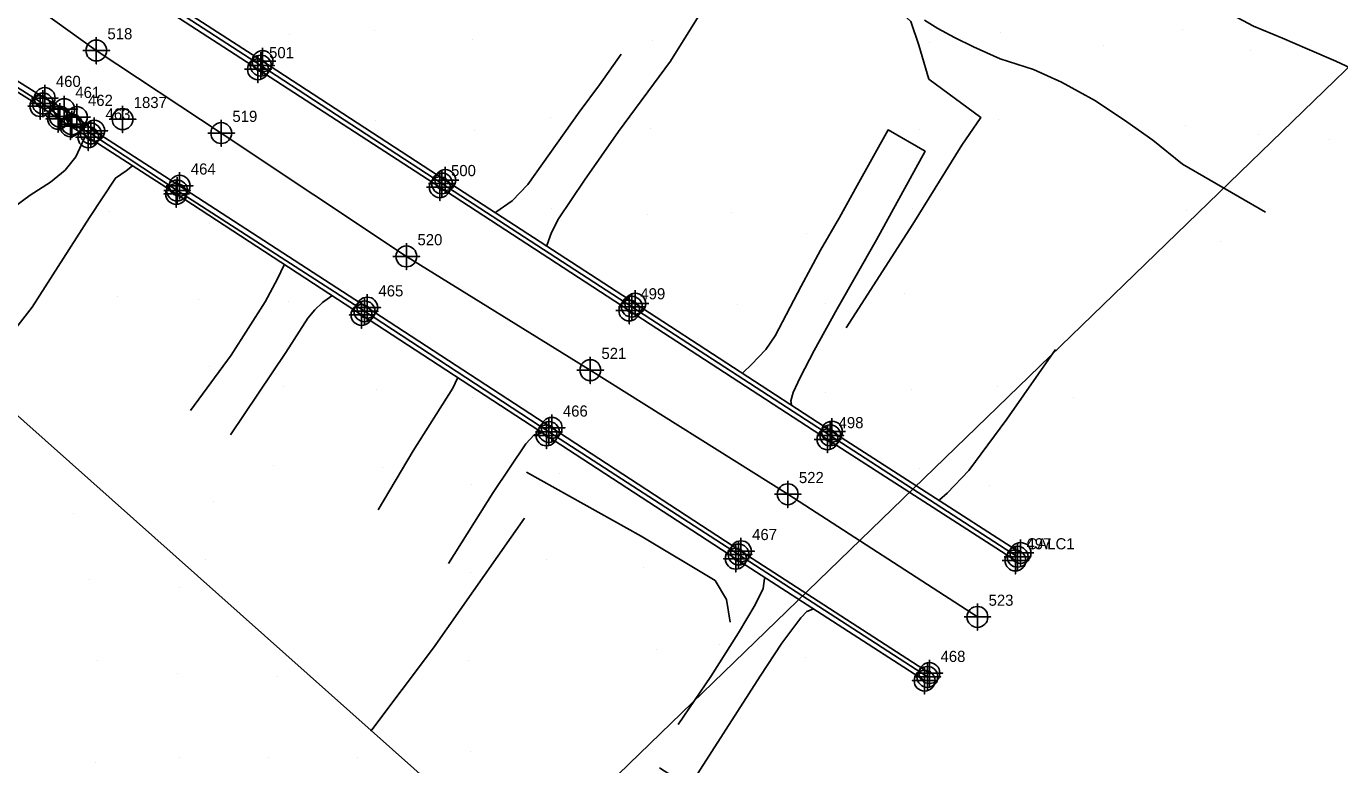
# Model space of a CAD drawing. Extents: x 1497074 to 1501343, y 481943 to 486114.
# Drawn here: x 1498449.4 to 1498743.8, y 484461 to 484626.5 of the extents above; entities that cross this region are included whole.
import ezdxf

# ---------------------------------------------------------------- set-up
doc = ezdxf.new("R2010")
doc.units = 0
for name, color, linetype in [('Exist DTM Crownline', 7, 'Continuous'), ('Exist DTM Crownline Cogo Number', 7, 'Continuous'), ('Exist DTM Crownline Cogo Point CELL', 7, 'Continuous'), ('Exist DTM Drainline', 7, 'Continuous'), ('Exist DTM Drainline Cogo Point CELL', 7, 'Continuous'), ('Exist DTM Regular Point CELL', 7, 'Continuous'), ('Exist DTM Regular Point Cogo Number', 7, 'Continuous'), ('Exist Roads Curbs', 7, 'Continuous'), ('Exist Roads Curbs Cogo Point CELL', 7, 'Continuous'), ('Exist Roads EOP', 7, 'Continuous'), ('Exist Roads EOP Cogo Number', 7, 'Continuous'), ('Exist Roads EOP Cogo Point CELL', 7, 'Continuous'), ('PH Exist DTM Boundary', 7, 'Continuous'), ('PH Exist DTM Breakline', 7, 'Continuous'), ('PH Exist DTM Point', 7, 'Continuous')]:
    doc.layers.add(name, color=color, linetype=linetype)

msp = doc.modelspace()

# ---------------------------------------------------------------- linework, layer by layer
at = {"layer": 'Exist DTM Crownline'}
msp.add_lwpolyline([(1498437.44, 484640.31), (1498444.09, 484636.17), (1498465.05, 484621.1), (1498493.07, 484602.59), (1498534.57, 484574.94), (1498575.81, 484549.45), (1498620.08, 484521.62), (1498662.61, 484494.12)], dxfattribs=at)
at = {"layer": 'Exist DTM Crownline Cogo Point CELL'}
for points in [[(1498465.05, 484624.1), (1498465.05, 484618.1), (1498465.05, 484621.1), (1498468.05, 484621.1), (1498462.05, 484621.1)], [(1498493.07, 484605.59), (1498493.07, 484599.59), (1498493.07, 484602.59), (1498496.07, 484602.59), (1498490.07, 484602.59)], [(1498534.57, 484577.94), (1498534.57, 484571.94), (1498534.57, 484574.94), (1498537.57, 484574.94), (1498531.57, 484574.94)], [(1498575.81, 484552.45), (1498575.81, 484546.45), (1498575.81, 484549.45), (1498578.81, 484549.45), (1498572.81, 484549.45)], [(1498620.08, 484524.62), (1498620.08, 484518.62), (1498620.08, 484521.62), (1498623.08, 484521.62), (1498617.08, 484521.62)], [(1498662.61, 484497.12), (1498662.61, 484491.12), (1498662.61, 484494.12), (1498665.61, 484494.12), (1498659.61, 484494.12)]]:
    msp.add_lwpolyline(points, dxfattribs=at)
for centre in [(1498465.05, 484621.1), (1498493.07, 484602.59), (1498534.57, 484574.94), (1498575.81, 484549.45), (1498620.08, 484521.62), (1498662.61, 484494.12)]:
    msp.add_circle(centre, 2.34, dxfattribs=at)
at = {"layer": 'Exist DTM Drainline'}
for points in [[(1498671.61, 484507.62), (1498629.62, 484534.81), (1498585.12, 484563.67), (1498542.56, 484591.3), (1498501.94, 484617.72), (1498481.42, 484631.07), (1498478.45, 484633.67)], [(1498456.84, 484606.28), (1498453.09, 484609.22), (1498440.58, 484617.04), (1498437.69, 484618.27), (1498435.85, 484618.97), (1498433.34, 484619.71), (1498431.51, 484619.86)], [(1498651.39, 484480.67), (1498609.06, 484508.13), (1498566.53, 484535.59), (1498525.19, 484562.64), (1498483.16, 484589.73), (1498463.82, 484602.49), (1498459.58, 484604.56)]]:
    msp.add_lwpolyline(points, dxfattribs=at)
at = {"layer": 'Exist DTM Drainline Cogo Point CELL'}
for points in [[(1498501.94, 484620.72), (1498501.94, 484614.72), (1498501.94, 484617.72), (1498504.94, 484617.72), (1498498.94, 484617.72)], [(1498453.09, 484612.22), (1498453.09, 484606.22), (1498453.09, 484609.22), (1498456.09, 484609.22), (1498450.09, 484609.22)], [(1498456.84, 484609.28), (1498456.84, 484603.28), (1498456.84, 484606.28), (1498459.84, 484606.28), (1498453.84, 484606.28)], [(1498459.58, 484607.56), (1498459.58, 484601.56), (1498459.58, 484604.56), (1498462.58, 484604.56), (1498456.58, 484604.56)], [(1498463.82, 484605.49), (1498463.82, 484599.49), (1498463.82, 484602.49), (1498466.82, 484602.49), (1498460.82, 484602.49)], [(1498542.56, 484594.3), (1498542.56, 484588.3), (1498542.56, 484591.3), (1498545.56, 484591.3), (1498539.56, 484591.3)], [(1498483.16, 484592.73), (1498483.16, 484586.73), (1498483.16, 484589.73), (1498486.16, 484589.73), (1498480.16, 484589.73)], [(1498585.12, 484566.67), (1498585.12, 484560.67), (1498585.12, 484563.67), (1498588.12, 484563.67), (1498582.12, 484563.67)], [(1498525.19, 484565.64), (1498525.19, 484559.64), (1498525.19, 484562.64), (1498528.19, 484562.64), (1498522.19, 484562.64)], [(1498566.53, 484538.59), (1498566.53, 484532.59), (1498566.53, 484535.59), (1498569.53, 484535.59), (1498563.53, 484535.59)], [(1498629.62, 484537.81), (1498629.62, 484531.81), (1498629.62, 484534.81), (1498632.62, 484534.81), (1498626.62, 484534.81)], [(1498609.06, 484511.13), (1498609.06, 484505.13), (1498609.06, 484508.13), (1498612.06, 484508.13), (1498606.06, 484508.13)], [(1498671.61, 484510.62), (1498671.61, 484504.62), (1498671.61, 484507.62), (1498674.61, 484507.62), (1498668.61, 484507.62)], [(1498651.39, 484483.67), (1498651.39, 484477.67), (1498651.39, 484480.67), (1498654.39, 484480.67), (1498648.39, 484480.67)]]:
    msp.add_lwpolyline(points, dxfattribs=at)
for centre in [(1498501.94, 484617.72), (1498453.09, 484609.22), (1498456.84, 484606.28), (1498459.58, 484604.56), (1498463.82, 484602.49), (1498542.56, 484591.3), (1498483.16, 484589.73), (1498525.19, 484562.64), (1498585.12, 484563.67), (1498566.53, 484535.59), (1498629.62, 484534.81), (1498609.06, 484508.13), (1498671.61, 484507.62), (1498651.39, 484480.67)]:
    msp.add_circle(centre, 2.34, dxfattribs=at)
at = {"layer": 'Exist DTM Regular Point CELL'}
msp.add_lwpolyline([(1498470.94, 484608.7), (1498470.94, 484602.7), (1498470.94, 484605.7), (1498473.94, 484605.7), (1498467.94, 484605.7)], dxfattribs=at)
msp.add_circle((1498470.94, 484605.7), 2.34, dxfattribs=at)
at = {"layer": 'Exist Roads Curbs'}
for points in [[(1498471.65, 484670.06), (1498469.12, 484665.71), (1498468.03, 484662.6), (1498467.33, 484660.25), (1498466.93, 484657.59), (1498466.7, 484652.99), (1498467.03, 484648.77), (1498467.52, 484646.54), (1498468.43, 484644.1), (1498469.9, 484641.63), (1498470.84, 484640.1), (1498473.5, 484637.52), (1498475.95, 484636), (1498482.11, 484631.72), (1498502.34, 484618.71), (1498543.3, 484592.05), (1498585.9, 484564.35), (1498630, 484535.66), (1498672.27, 484508.46)], [(1498431.18, 484618.93), (1498433.55, 484618.74), (1498435.81, 484618.12), (1498437.29, 484617.53), (1498440.2, 484616.21), (1498452.5, 484608.64), (1498456.49, 484605.77), (1498459.25, 484604.12), (1498463.26, 484601.65), (1498482.96, 484588.94), (1498524.52, 484561.81), (1498565.99, 484534.81), (1498608.43, 484507.17), (1498650.76, 484479.84)]]:
    msp.add_lwpolyline(points, dxfattribs=at)
at = {"layer": 'Exist Roads Curbs Cogo Point CELL'}
for points in [[(1498502.34, 484621.71), (1498502.34, 484615.71), (1498502.34, 484618.71), (1498499.61, 484618.71), (1498505.34, 484618.71)], [(1498452.5, 484611.64), (1498452.5, 484605.64), (1498452.5, 484608.64), (1498449.77, 484608.64), (1498455.5, 484608.64)], [(1498456.49, 484608.77), (1498456.49, 484602.77), (1498456.49, 484605.77), (1498453.76, 484605.77), (1498459.49, 484605.77)], [(1498459.25, 484607.12), (1498459.25, 484601.12), (1498459.25, 484604.12), (1498456.52, 484604.12), (1498462.25, 484604.12)], [(1498463.26, 484604.65), (1498463.26, 484598.65), (1498463.26, 484601.65), (1498460.53, 484601.65), (1498466.26, 484601.65)], [(1498543.3, 484595.05), (1498543.3, 484589.05), (1498543.3, 484592.05), (1498540.57, 484592.05), (1498546.3, 484592.05)], [(1498482.96, 484591.94), (1498482.96, 484585.94), (1498482.96, 484588.94), (1498480.23, 484588.94), (1498485.96, 484588.94)], [(1498585.9, 484567.35), (1498585.9, 484561.35), (1498585.9, 484564.35), (1498583.17, 484564.35), (1498588.9, 484564.35)], [(1498524.52, 484564.81), (1498524.52, 484558.81), (1498524.52, 484561.81), (1498521.79, 484561.81), (1498527.52, 484561.81)], [(1498565.99, 484537.81), (1498565.99, 484531.81), (1498565.99, 484534.81), (1498563.26, 484534.81), (1498568.99, 484534.81)], [(1498630, 484538.66), (1498630, 484532.66), (1498630, 484535.66), (1498627.27, 484535.66), (1498633, 484535.66)], [(1498672.27, 484511.46), (1498672.27, 484505.46), (1498672.27, 484508.46), (1498669.54, 484508.46), (1498675.27, 484508.46)], [(1498608.43, 484510.17), (1498608.43, 484504.17), (1498608.43, 484507.17), (1498605.7, 484507.17), (1498611.43, 484507.17)], [(1498650.76, 484482.84), (1498650.76, 484476.84), (1498650.76, 484479.84), (1498648.03, 484479.84), (1498653.76, 484479.84)]]:
    msp.add_lwpolyline(points, dxfattribs=at)
for centre in [(1498502.34, 484618.71), (1498452.5, 484608.64), (1498456.49, 484605.77), (1498459.25, 484604.12), (1498463.26, 484601.65), (1498543.3, 484592.05), (1498482.96, 484588.94), (1498585.9, 484564.35), (1498524.52, 484561.81), (1498565.99, 484534.81), (1498630, 484535.66), (1498672.27, 484508.46), (1498608.43, 484507.17), (1498650.76, 484479.84)]:
    msp.add_circle(centre, 2.34, dxfattribs=at)
at = {"layer": 'Exist Roads EOP'}
for points in [[(1498671.12, 484506.76), (1498628.99, 484533.93), (1498584.54, 484562.81), (1498542.08, 484590.44), (1498501.29, 484616.88), (1498481.13, 484629.93), (1498477.24, 484632.12), (1498474.48, 484633.92), (1498472.12, 484636.11), (1498469.35, 484638.86), (1498468.21, 484640.34), (1498466.66, 484643.08), (1498465.57, 484646.04), (1498464.92, 484648.33), (1498464.6, 484652.76), (1498464.81, 484657.5), (1498465.25, 484660.35), (1498465.82, 484663.04), (1498467.08, 484666.5), (1498469.5, 484670.86)], [(1498431.57, 484621.11), (1498433.52, 484620.75), (1498436.39, 484620.14), (1498438.22, 484619.42), (1498441.01, 484618.16), (1498453.49, 484610.43), (1498457.85, 484607.96), (1498460.69, 484606.18), (1498464.61, 484603.11), (1498483.74, 484590.79), (1498525.81, 484563.47), (1498567.17, 484536.52), (1498609.6, 484508.85), (1498651.84, 484481.53)]]:
    msp.add_lwpolyline(points, dxfattribs=at)
at = {"layer": 'Exist Roads EOP Cogo Point CELL'}
for points in [[(1498501.29, 484619.88), (1498501.29, 484613.88), (1498501.29, 484616.88), (1498504.29, 484616.88), (1498498.29, 484616.88)], [(1498453.49, 484613.43), (1498453.49, 484607.43), (1498453.49, 484610.43), (1498456.49, 484610.43), (1498450.49, 484610.43)], [(1498457.85, 484610.96), (1498457.85, 484604.96), (1498457.85, 484607.96), (1498460.85, 484607.96), (1498454.85, 484607.96)], [(1498460.69, 484609.18), (1498460.69, 484603.18), (1498460.69, 484606.18), (1498463.69, 484606.18), (1498457.69, 484606.18)], [(1498464.61, 484606.11), (1498464.61, 484600.11), (1498464.61, 484603.11), (1498467.61, 484603.11), (1498461.61, 484603.11)], [(1498483.74, 484593.79), (1498483.74, 484587.79), (1498483.74, 484590.79), (1498486.74, 484590.79), (1498480.74, 484590.79)], [(1498542.08, 484593.44), (1498542.08, 484587.44), (1498542.08, 484590.44), (1498545.08, 484590.44), (1498539.08, 484590.44)], [(1498525.81, 484566.47), (1498525.81, 484560.47), (1498525.81, 484563.47), (1498528.81, 484563.47), (1498522.81, 484563.47)], [(1498584.54, 484565.81), (1498584.54, 484559.81), (1498584.54, 484562.81), (1498587.54, 484562.81), (1498581.54, 484562.81)], [(1498567.17, 484539.52), (1498567.17, 484533.52), (1498567.17, 484536.52), (1498570.17, 484536.52), (1498564.17, 484536.52)], [(1498628.99, 484536.93), (1498628.99, 484530.93), (1498628.99, 484533.93), (1498631.99, 484533.93), (1498625.99, 484533.93)], [(1498609.6, 484511.85), (1498609.6, 484505.85), (1498609.6, 484508.85), (1498612.6, 484508.85), (1498606.6, 484508.85)], [(1498671.12, 484509.76), (1498671.12, 484503.76), (1498671.12, 484506.76), (1498674.12, 484506.76), (1498668.12, 484506.76)], [(1498671.12, 484509.76), (1498671.12, 484503.76), (1498671.12, 484506.76), (1498674.12, 484506.76), (1498668.12, 484506.76)], [(1498651.84, 484484.53), (1498651.84, 484478.53), (1498651.84, 484481.53), (1498654.84, 484481.53), (1498648.84, 484481.53)]]:
    msp.add_lwpolyline(points, dxfattribs=at)
for centre in [(1498501.29, 484616.88), (1498453.49, 484610.43), (1498457.85, 484607.96), (1498460.69, 484606.18), (1498464.61, 484603.11), (1498483.74, 484590.79), (1498542.08, 484590.44), (1498525.81, 484563.47), (1498584.54, 484562.81), (1498567.17, 484536.52), (1498628.99, 484533.93), (1498609.6, 484508.85), (1498671.12, 484506.76), (1498671.12, 484506.76), (1498651.84, 484481.53)]:
    msp.add_circle(centre, 2.34, dxfattribs=at)
at = {"layer": 'PH Exist DTM Boundary'}
for points in [[(1498186.43, 484771.69), (1498560.82, 484438.23), (1498782.89, 484653.31), (1498924.23, 484841.06), (1498545.19, 485168.9), (1498406.94, 484985.26)], [(1497810.36, 484407.45), (1498181.14, 484070.49), (1498560.82, 484438.23), (1498186.43, 484771.69)]]:
    msp.add_lwpolyline(points, close=True, dxfattribs=at)
at = {"layer": 'PH Exist DTM Breakline'}
for points in [[(1498631.32, 484672.18), (1498638.78, 484668.07), (1498645.74, 484665.05), (1498652.08, 484662.44), (1498658.02, 484661.42), (1498665.09, 484661.49), (1498671.48, 484661.91), (1498678.83, 484660.27), (1498685.67, 484657.51), (1498691.48, 484653.45), (1498698.1, 484647.25), (1498704.19, 484641.46), (1498707.27, 484638.54), (1498711.94, 484634.11), (1498717.33, 484630.4), (1498724.54, 484626.58), (1498731.01, 484623.87), (1498736.56, 484621.51), (1498742.96, 484618.72), (1498747.59, 484616.58)], [(1498633.18, 484558.95), (1498648.11, 484582.16), (1498659.09, 484599.9), (1498663.4, 484606.06), (1498651.69, 484614.71), (1498649.44, 484622.31), (1498647.66, 484627.57), (1498641.26, 484633.6), (1498621.45, 484644.43)], [(1498566.07, 484577.37), (1498567.08, 484580.29), (1498568.7, 484583.4), (1498574.48, 484592.02), (1498582.14, 484602.93), (1498593.77, 484618.72), (1498601.85, 484631.65), (1498594, 484636.69)], [(1498727.2, 484584.84), (1498708.57, 484595.61), (1498701.95, 484600.97), (1498696.09, 484605.11), (1498689.09, 484609.83), (1498681.43, 484613.97), (1498675.21, 484616.82), (1498667.71, 484619.25), (1498661.7, 484621.92), (1498657.49, 484624.01), (1498653.72, 484626), (1498650.77, 484627.88)], [(1498582.75, 484620.28), (1498577.89, 484613.43), (1498573.35, 484607.26), (1498561.81, 484591.04), (1498558.32, 484587.43), (1498554.65, 484584.88)], [(1498436.52, 484572.85), (1498446.49, 484585.92), (1498450.23, 484588.64), (1498454.81, 484591.58), (1498458.06, 484594.29), (1498460.46, 484597.24), (1498462.65, 484601.96)], [(1498620.92, 484541.75), (1498620.75, 484542.55), (1498621.28, 484544.44), (1498622.9, 484547.76), (1498625.97, 484553.82), (1498631.15, 484563.2), (1498639.98, 484578.65), (1498650.89, 484598.5), (1498642.59, 484603.31), (1498635.66, 484590.87), (1498631.71, 484583.68), (1498627.42, 484576.32), (1498623.08, 484568.28), (1498617.27, 484557.11), (1498615.15, 484554.04), (1498611.98, 484550.71), (1498610.12, 484548.93)], [(1498473.18, 484595.21), (1498471.77, 484594.13), (1498469.35, 484592.49), (1498463.5, 484583.68), (1498450.69, 484563.57), (1498439.11, 484548.76), (1498427.72, 484557.14)], [(1498486.15, 484540.43), (1498495.3, 484552.79), (1498502.95, 484564.76), (1498505.71, 484569.95), (1498507.16, 484573.06)], [(1498517.85, 484566.09), (1498515.78, 484564.59), (1498514.08, 484562.97), (1498512.5, 484561.11), (1498507.55, 484553.4), (1498495.11, 484534.91)], [(1498654.08, 484520.39), (1498655.81, 484521.84), (1498660.68, 484526.93), (1498669.23, 484538.48), (1498680.1, 484554.09)], [(1498546.07, 484547.66), (1498545.02, 484545.38), (1498536.09, 484531.34), (1498528.26, 484518.1)], [(1498565, 484535.39), (1498563.25, 484534.98), (1498561.33, 484532.95), (1498554.02, 484522.03), (1498544.05, 484506.08)], [(1498607.16, 484492.96), (1498606.33, 484498.01), (1498603.79, 484502.31), (1498587.18, 484512.25), (1498561.51, 484526.58)], [(1498561.03, 484516.25), (1498540.69, 484487.18), (1498526.62, 484468.51)], [(1498595.53, 484469.98), (1498602.83, 484480.76), (1498609.05, 484490.56), (1498612.78, 484496.8), (1498614.56, 484500.49), (1498614.85, 484502.74)], [(1498625.67, 484495.87), (1498624.38, 484495.33), (1498623.01, 484493.91), (1498618.75, 484488.23), (1498613.89, 484480.84), (1498598, 484456.01), (1498591.3, 484460.28)]]:
    msp.add_lwpolyline(points, dxfattribs=at)
at = {"layer": 'PH Exist DTM Point'}
for p, q in [((1498527.45, 484625.5), (1498527.45, 484625.5)), ((1498708.52, 484625.81), (1498708.52, 484625.81)), ((1498508.41, 484624.59), (1498508.41, 484624.59)), ((1498549.43, 484623.62), (1498549.43, 484623.62)), ((1498589.79, 484623.25), (1498589.79, 484623.25)), ((1498651.78, 484622.81), (1498651.78, 484622.81)), ((1498667.74, 484625.08), (1498667.74, 484625.08)), ((1498690.87, 484622.22), (1498690.87, 484622.22)), ((1498723.86, 484621), (1498723.86, 484621)), ((1498527.63, 484605.45), (1498527.63, 484605.45)), ((1498566.86, 484606.07), (1498566.86, 484606.07)), ((1498667.23, 484605.71), (1498667.23, 484605.71)), ((1498549.81, 484603.26), (1498549.81, 484603.26)), ((1498589.38, 484603.67), (1498589.38, 484603.67)), ((1498649.59, 484603.48), (1498649.59, 484603.48)), ((1498709.2, 484604.26), (1498709.2, 484604.26)), ((1498725.72, 484602.35), (1498725.72, 484602.35)), ((1498741.48, 484601.24), (1498741.48, 484601.24)), ((1498468, 484584.98), (1498468, 484584.98)), ((1498567.16, 484585.78), (1498567.16, 484585.78)), ((1498588.71, 484584.3), (1498588.71, 484584.3)), ((1498607.37, 484584.68), (1498607.37, 484584.68)), ((1498648.09, 484585.69), (1498648.09, 484585.69)), ((1498709.39, 484585.26), (1498709.39, 484585.26)), ((1498490.35, 484582.3), (1498490.35, 484582.3)), ((1498624.35, 484580.12), (1498624.35, 484580.12)), ((1498717.06, 484578.28), (1498717.06, 484578.28)), ((1498646.18, 484566.71), (1498646.18, 484566.71)), ((1498469.76, 484565.95), (1498469.76, 484565.95)), ((1498487.95, 484565.3), (1498487.95, 484565.3)), ((1498508.16, 484564.83), (1498508.16, 484564.83)), ((1498591.08, 484565.72), (1498591.08, 484565.72)), ((1498608.79, 484564.23), (1498608.79, 484564.23)), ((1498628.61, 484564.4), (1498628.61, 484564.4)), ((1498522.61, 484559.62), (1498522.61, 484559.62)), ((1498490.46, 484550.22), (1498490.46, 484550.22)), ((1498507.1, 484545.83), (1498507.1, 484545.83)), ((1498527.85, 484545.05), (1498527.85, 484545.05)), ((1498549.38, 484543.31), (1498549.38, 484543.31)), ((1498628.62, 484544.5), (1498628.62, 484544.5)), ((1498647.79, 484545.18), (1498647.79, 484545.18)), ((1498667.13, 484545.8), (1498667.13, 484545.8)), ((1498684.14, 484543.39), (1498684.14, 484543.39)), ((1498504.69, 484528.11), (1498504.69, 484528.11)), ((1498529.33, 484527.6), (1498529.33, 484527.6)), ((1498568.84, 484526.24), (1498568.84, 484526.24)), ((1498649.7, 484527.42), (1498649.7, 484527.42)), ((1498549.16, 484523.88), (1498549.16, 484523.88)), ((1498665.28, 484523.53), (1498665.28, 484523.53)), ((1498491.25, 484520), (1498491.25, 484520)), ((1498459.86, 484517.2), (1498459.86, 484517.2)), ((1498489.5, 484506.93), (1498489.5, 484506.93)), ((1498565.99, 484506.89), (1498565.99, 484506.89)), ((1498587.82, 484505.15), (1498587.82, 484505.15)), ((1498463.61, 484502.6), (1498463.61, 484502.6)), ((1498548.89, 484504.14), (1498548.89, 484504.14)), ((1498483.7, 484500.77), (1498483.7, 484500.77)), ((1498604.79, 484488.03), (1498604.79, 484488.03)), ((1498465.3, 484484.34), (1498465.3, 484484.34)), ((1498548.6, 484484.41), (1498548.6, 484484.41)), ((1498590.64, 484486.77), (1498590.64, 484486.77)), ((1498624.05, 484485.02), (1498624.05, 484485.02)), ((1498483.33, 484481.49), (1498483.33, 484481.49)), ((1498505.61, 484480.7), (1498505.61, 484480.7)), ((1498548.87, 484464.04), (1498548.87, 484464.04)), ((1498464.89, 484461.39), (1498464.89, 484461.39)), ((1498483.71, 484462.71), (1498483.71, 484462.71)), ((1498503.61, 484462.6), (1498503.61, 484462.6)), ((1498523.66, 484462.56), (1498523.66, 484462.56))]:
    msp.add_line(p, q, dxfattribs=at)

# ---------------------------------------------------------------- texts
at = {"layer": 'Exist DTM Crownline Cogo Number'}
for s, p in [('518', (1498467.55, 484623.6)), ('519', (1498495.57, 484605.09)), ('520', (1498537.07, 484577.44)), ('521', (1498578.31, 484551.95)), ('522', (1498622.58, 484524.12)), ('523', (1498665.11, 484496.62))]:
    msp.add_text(s, height=2.5, dxfattribs=at).set_placement(p)
at = {"layer": 'Exist DTM Regular Point Cogo Number'}
msp.add_text('1837', height=2.5, dxfattribs=at).set_placement((1498473.44, 484608.2))
at = {"layer": 'Exist Roads EOP Cogo Number'}
for s, p in [('501', (1498503.79, 484619.38)), ('460', (1498455.99, 484612.93)), ('461', (1498460.35, 484610.46)), ('462', (1498463.19, 484608.68)), ('463', (1498467.11, 484605.61)), ('464', (1498486.24, 484593.29)), ('500', (1498544.58, 484592.94)), ('465', (1498528.31, 484565.97)), ('499', (1498587.04, 484565.32)), ('466', (1498569.67, 484539.03)), ('498', (1498631.49, 484536.43)), ('467', (1498612.1, 484511.35)), ('497', (1498673.62, 484509.27)), ('CALC1', (1498673.62, 484509.27)), ('468', (1498654.34, 484484.03))]:
    msp.add_text(s, height=2.5, dxfattribs=at).set_placement(p)

doc.saveas('drawing.dxf')
